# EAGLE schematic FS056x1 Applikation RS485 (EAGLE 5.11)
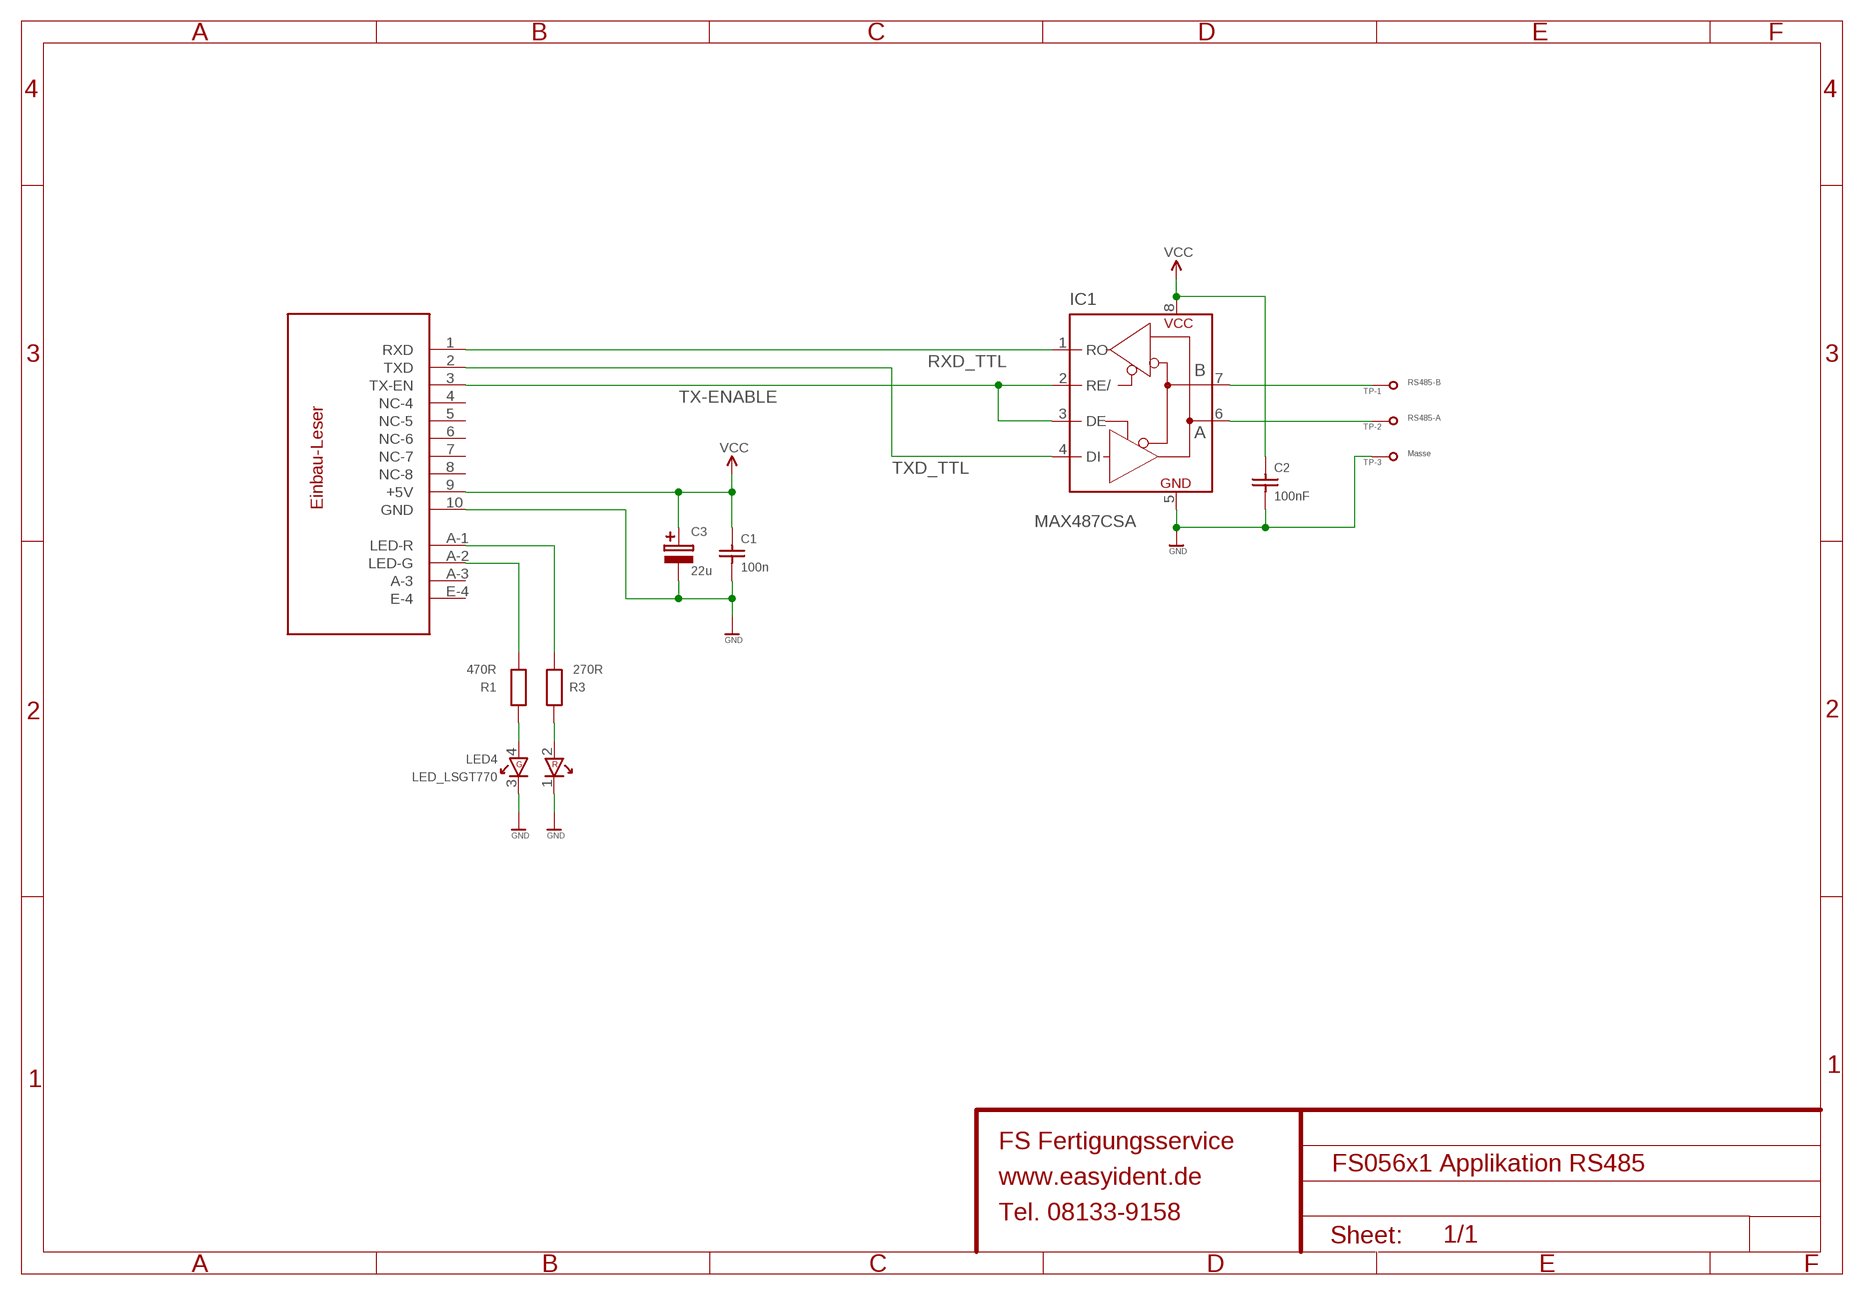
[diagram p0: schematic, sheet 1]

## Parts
C1  100n  C-0603  [0603]
C2  100nF  C-0603  [0603]
C3  22u  C-TAJA  [TAJA]
IC1  MAX487CSA  [SO-08]
LED4  LED_LSGT770  [LED_LSG-T770]
MODUL1  PHG-LESER  [PHG-LESER]
R1  470R  R-0603  [0603]
R3  270R  R-0603  [0603]
TP-1  RS485-B  TRIGGER  [TRIGGER]
TP-2  RS485-A  TRIGGER  [TRIGGER]
TP-3  Masse  TRIGGER  [TRIGGER]

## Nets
GND: C1.2 C2.2 C3.M-(-) IC1.5(GND) LED4.1(C1-P1) LED4.3(C2-P3) MODUL1.10(GND) TP-3.1
LED-GRÜN: MODUL1.A-2(LED-G) R1.1
LED-ROT: MODUL1.A-1(LED-R) R3.1
N$2: IC1.7(B) TP-1.1
N$3: LED4.4(A2-P4) R1.2
N$4: LED4.2(A1-P2) R3.2
N$5: IC1.6(A) TP-2.1
RXD_TTL: IC1.1(RO) MODUL1.1(RXD)
TX-ENABLE: IC1.2(RE/) IC1.3(DE) MODUL1.3(TX-EN)
TXD_TTL: IC1.4(DI) MODUL1.2(TXD)
VCC: C1.1 C2.1 C3.P+(+) IC1.8(VCC) MODUL1.9(+5V)
Unconnected: MODUL1.4(NC-4) MODUL1.5(NC-5) MODUL1.6(NC-6) MODUL1.7(NC-7) MODUL1.8(NC-8) MODUL1.A-3 MODUL1.E-4

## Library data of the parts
C1 C2 = 5-FS-Library:C-0603
C3 = 5-FS-Kondensatoren:C-TAJA
IC1 = 5-FS-Library:MAX487CSA
LED4 = 5-FS-Library:LED_LSGT770
MODUL1 = 5-FS-Library:PHG-LESER
R1 R3 = 5-FS-Library:R-0603: SMD Widerstand Bauform 0603
TP-1-TP-3 = 5-FS-Library:TRIGGER: Trigger Testpunkt 1mm Durckmesser Durchmesser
